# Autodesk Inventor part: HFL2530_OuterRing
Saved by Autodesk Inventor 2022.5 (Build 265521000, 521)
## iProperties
Created: 2024-12
Part Number: HFL2530_OuterRing
Material: Generic
Document SubType Name: Modeling
Designer: AdminForWorker
Density: 1 g/cm^3
Appearance: Default
Title: HFL2530_OuterRing
Author: AdminForWorker
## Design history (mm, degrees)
feature "Body1"
body "Solid1"
